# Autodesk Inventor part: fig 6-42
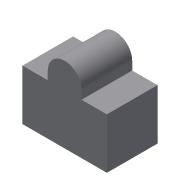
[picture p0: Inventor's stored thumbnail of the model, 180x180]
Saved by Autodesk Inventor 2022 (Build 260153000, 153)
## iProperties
Created: 2005-12
Part Number: fig 6-42
Document SubType Name: Modeling
Designer: CADCIM
Density: 1 g/cm^3
Material: Generic
Appearance: Default
Author: CADCIM
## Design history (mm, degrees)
sketch "Sketch1"
  geometry: L1 (10, 15)-(25, 15); L2 (25, 15)-(25, -15); L3 (25, -15)-(-25, -15); L4 (-25, -15)-(-25, 15); L5 (-25, 15)-(-10, 15); L6 (10, 15)-(10, 30); L7 (10, 30)-(-10, 30); L8 (-10, 30)-(-10, 15)
  constraints: 16 end point, 3 parallel, 3 perpendicular, 2 equal length, 1 collinear, 1 horizontal
  dimensions: "d0" = 50 distance of L2.end L3.end; "d2" = 30 distance of L1.end L2.end; "d3" = 15 distance of L1.start L1.end; "d11" = 15 distance of L7.end L5.end
extrude "Extrusion1" new body sketch "Sketch1" stored distance "d7" = 30; taper "d8" = 0 deg
fillet "Fillet5"
body "Solid1"
